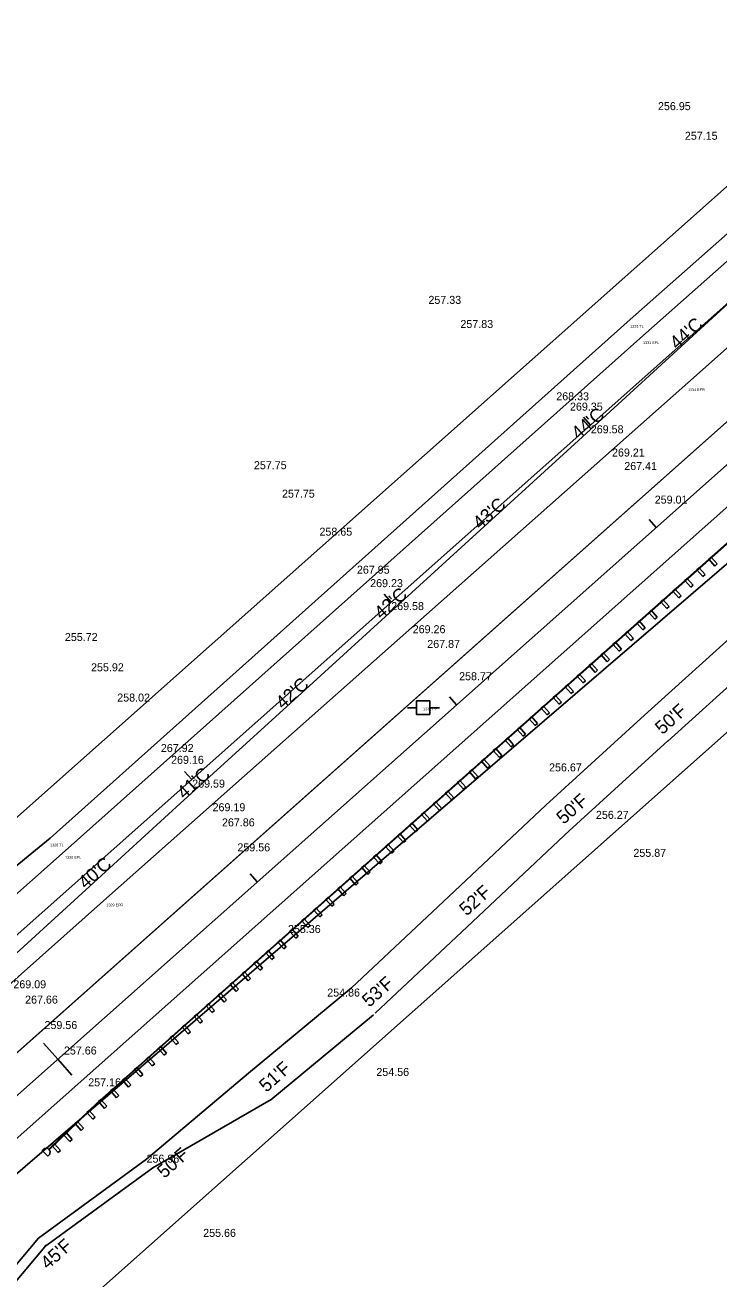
# Model space of a CAD drawing. Extents: x 49683 to 58852, y 49525 to 54803.
# Drawn here: x 52930.9 to 53191, y 50894.8 to 51364.8 of the extents above; entities that cross this region are included whole.
import ezdxf

# ---------------------------------------------------------------- set-up
doc = ezdxf.new("R2010")
doc.units = 0
for name, color, linetype in [('Level 1', 7, 'Continuous'), ('Level 11', 7, 'Continuous'), ('Level 13', 7, 'Continuous'), ('Level 18', 7, 'Continuous'), ('Level 19', 7, 'Continuous'), ('Level 20', 7, 'Continuous'), ('Level 27', 7, 'Continuous'), ('Level 3', 7, 'Continuous'), ('Level 32', 7, 'Continuous'), ('Level 33', 7, 'Continuous'), ('Level 48', 7, 'Continuous'), ('Level 53', 7, 'Continuous'), ('Level 59', 7, 'Continuous'), ('Level 61', 7, 'Continuous'), ('Level 9', 7, 'Continuous')]:
    doc.layers.add(name, color=color, linetype=linetype)

# ---------------------------------------------------------------- blocks, each defined once
blk = doc.blocks.new('PP')
at = {"layer": 'Level 9'}
for p, q in [((2.53, 2.45), (-2.47, 2.45)), ((-2.47, 2.45), (-2.47, -2.55)), ((2.53, -2.55), (2.53, 2.45)), ((-5.91, -0.11), (-2.44, -0.11)), ((-2.47, -2.55), (2.53, -2.55)), ((2.45, -0.11), (6.09, -0.11))]:
    blk.add_line(p, q, dxfattribs=at)

msp = doc.modelspace()

# ---------------------------------------------------------------- linework, layer by layer
at = {"layer": 'Level 1'}
for p, q in [((52544.81, 50683.3), (55534.58, 53340.86)), ((53142.87, 51214.91), (53140.21, 51217.9)), ((53068.13, 51148.47), (53065.47, 51151.46)), ((52993.38, 51082.03), (52990.73, 51085.02))]:
    msp.add_line(p, q, dxfattribs=at)
at = {"layer": 'Level 11'}
for p, q in [((53157.7, 51254.45), (53424.49, 51490.93)), ((52940.3, 51059.99), (53157.7, 51254.45)), ((52882.73, 50895.61), (53245.86, 51207.55)), ((52688.43, 50854.08), (52940.3, 51059.99))]:
    msp.add_line(p, q, dxfattribs=at)
at = {"layer": 'Level 13'}
for p, q in [((52637.37, 50809.73), (53363.85, 51455.49)), ((53407.7, 51406.16), (52566.74, 50658.64))]:
    msp.add_line(p, q, dxfattribs=at)
at = {"layer": 'Level 18'}
for p, q in [((53175.25, 51242.97), (53212.1, 51276.77)), ((53138.39, 51209.17), (53175.25, 51242.97)), ((53101.44, 51175.48), (53138.39, 51209.17)), ((53064.5, 51141.78), (53101.44, 51175.48)), ((53027.57, 51108.07), (53064.5, 51141.78)), ((53163.11, 51106.1), (53200.16, 51139.69)), ((53171.84, 51096.47), (53208.89, 51130.05)), ((52990.61, 51074.38), (53027.57, 51108.07)), ((53126.12, 51072.45), (53163.11, 51106.1)), ((53134.87, 51062.84), (53171.86, 51096.49)), ((52953.66, 51040.7), (52990.61, 51074.38)), ((53089.73, 51038.14), (53126.12, 51072.45)), ((53098.65, 51028.68), (53135.04, 51063)), ((52916.76, 51006.95), (52953.66, 51040.7)), ((53053.26, 51003.9), (53089.73, 51038.14)), ((53062.16, 50994.42), (53098.63, 51028.66)), ((53014.71, 50972.01), (53053.26, 51003.9)), ((53023, 50961.99), (53061.55, 50993.88)), ((52976.49, 50939.75), (53014.71, 50972.01)), ((52978.85, 50936.52), (53023.1, 50962.08)), ((52935.91, 50910.15), (52976.49, 50939.75)), ((52938.27, 50906.92), (52978.85, 50936.52)), ((52903.42, 50871.43), (52935.91, 50910.15)), ((52906.49, 50868.86), (52938.97, 50907.58))]:
    msp.add_line(p, q, dxfattribs=at)
at = {"layer": 'Level 19'}
for p, q in [((52714.15, 50773.62), (54181.77, 52078.16)), ((53167.42, 51176.52), (53164.76, 51179.51)), ((53092.67, 51110.08), (53090.02, 51113.07)), ((53017.93, 51043.65), (53015.28, 51046.64)), ((52943.19, 50977.21), (52937.88, 50983.19)), ((52943.19, 50977.21), (52948.51, 50971.23))]:
    msp.add_line(p, q, dxfattribs=at)
at = {"layer": 'Level 20'}
for p, q in [((52706.17, 50782.58), (53452.43, 51445.92)), ((52722.12, 50764.65), (53468.37, 51427.98))]:
    msp.add_line(p, q, dxfattribs=at)
at = {"layer": 'Level 27'}
for p, q in [((52957.81, 50960.77), (53475.02, 51420.51)), ((52957.97, 50960.58), (53475.18, 51420.32)), ((53187.13, 51164.61), (53188.01, 51165.39)), ((53189.39, 51162.06), (53187.13, 51164.61)), ((53188.01, 51165.39), (53190.27, 51162.85)), ((53190.27, 51162.85), (53189.39, 51162.06)), ((53178.16, 51156.63), (53179.04, 51157.42)), ((53179.04, 51157.42), (53181.3, 51154.88)), ((53182.64, 51160.62), (53183.53, 51161.41)), ((53184.9, 51158.08), (53182.64, 51160.62)), ((53183.53, 51161.41), (53185.79, 51158.86)), ((53185.79, 51158.86), (53184.9, 51158.08)), ((53173.67, 51152.65), (53174.56, 51153.43)), ((53175.93, 51150.11), (53173.67, 51152.65)), ((53174.56, 51153.43), (53176.82, 51150.89)), ((53180.42, 51154.09), (53178.16, 51156.63)), ((53181.3, 51154.88), (53180.42, 51154.09)), ((53169.19, 51148.66), (53170.07, 51149.45)), ((53171.45, 51146.12), (53169.19, 51148.66)), ((53170.07, 51149.45), (53172.33, 51146.91)), ((53176.82, 51150.89), (53175.93, 51150.11)), ((53164.71, 51144.68), (53165.59, 51145.46)), ((53166.96, 51142.13), (53164.71, 51144.68)), ((53165.59, 51145.46), (53167.85, 51142.92)), ((53167.85, 51142.92), (53166.96, 51142.13)), ((53172.33, 51146.91), (53171.45, 51146.12)), ((53160.22, 51140.69), (53161.1, 51141.47)), ((53162.48, 51138.15), (53160.22, 51140.69)), ((53161.1, 51141.47), (53163.36, 51138.93)), ((53163.36, 51138.93), (53162.48, 51138.15)), ((53151.25, 51132.72), (53152.14, 51133.5)), ((53152.14, 51133.5), (53154.39, 51130.96)), ((53155.74, 51136.7), (53156.62, 51137.49)), ((53157.99, 51134.16), (53155.74, 51136.7)), ((53156.62, 51137.49), (53158.88, 51134.95)), ((53158.88, 51134.95), (53157.99, 51134.16)), ((53146.77, 51128.73), (53147.65, 51129.52)), ((53149.03, 51126.19), (53146.77, 51128.73)), ((53147.65, 51129.52), (53149.91, 51126.97)), ((53153.51, 51130.18), (53151.25, 51132.72)), ((53154.39, 51130.96), (53153.51, 51130.18)), ((53142.28, 51124.74), (53143.17, 51125.53)), ((53144.54, 51122.2), (53142.28, 51124.74)), ((53143.17, 51125.53), (53145.43, 51122.99)), ((53149.91, 51126.97), (53149.03, 51126.19)), ((53137.8, 51120.76), (53138.68, 51121.54)), ((53140.06, 51118.22), (53137.8, 51120.76)), ((53138.68, 51121.54), (53140.94, 51119)), ((53145.43, 51122.99), (53144.54, 51122.2)), ((53133.31, 51116.77), (53134.2, 51117.56)), ((53135.57, 51114.23), (53133.31, 51116.77)), ((53134.2, 51117.56), (53136.46, 51115.02)), ((53136.46, 51115.02), (53135.57, 51114.23)), ((53140.94, 51119), (53140.06, 51118.22)), ((53128.83, 51112.79), (53129.71, 51113.57)), ((53131.09, 51110.24), (53128.83, 51112.79)), ((53129.71, 51113.57), (53131.97, 51111.03)), ((53131.97, 51111.03), (53131.09, 51110.24)), ((53119.86, 51104.81), (53120.74, 51105.6)), ((53120.74, 51105.6), (53123, 51103.06)), ((53124.35, 51108.8), (53125.23, 51109.58)), ((53126.6, 51106.26), (53124.35, 51108.8)), ((53125.23, 51109.58), (53127.49, 51107.04)), ((53127.49, 51107.04), (53126.6, 51106.26)), ((53115.38, 51100.83), (53116.26, 51101.61)), ((53117.63, 51098.29), (53115.38, 51100.83)), ((53116.26, 51101.61), (53118.52, 51099.07)), ((53122.12, 51102.27), (53119.86, 51104.81)), ((53123, 51103.06), (53122.12, 51102.27)), ((53110.89, 51096.84), (53111.78, 51097.63)), ((53113.15, 51094.3), (53110.89, 51096.84)), ((53111.78, 51097.63), (53114.03, 51095.08)), ((53118.52, 51099.07), (53117.63, 51098.29)), ((53106.41, 51092.86), (53107.29, 51093.64)), ((53108.67, 51090.31), (53106.41, 51092.86)), ((53107.29, 51093.64), (53109.55, 51091.1)), ((53109.55, 51091.1), (53108.67, 51090.31)), ((53114.03, 51095.08), (53113.15, 51094.3)), ((53101.92, 51088.87), (53102.81, 51089.65)), ((53104.18, 51086.33), (53101.92, 51088.87)), ((53102.81, 51089.65), (53105.06, 51087.11)), ((53105.06, 51087.11), (53104.18, 51086.33)), ((53092.95, 51080.9), (53093.84, 51081.68)), ((53093.84, 51081.68), (53096.1, 51079.14)), ((53097.44, 51084.88), (53098.32, 51085.67)), ((53099.7, 51082.34), (53097.44, 51084.88)), ((53098.32, 51085.67), (53100.58, 51083.13)), ((53100.58, 51083.13), (53099.7, 51082.34)), ((53088.47, 51076.91), (53089.35, 51077.7)), ((53090.73, 51074.37), (53088.47, 51076.91)), ((53089.35, 51077.7), (53091.61, 51075.15)), ((53095.21, 51078.36), (53092.95, 51080.9)), ((53096.1, 51079.14), (53095.21, 51078.36)), ((53083.99, 51072.92), (53084.87, 51073.71)), ((53086.24, 51070.38), (53083.99, 51072.92)), ((53084.87, 51073.71), (53087.13, 51071.17)), ((53091.61, 51075.15), (53090.73, 51074.37)), ((53079.5, 51068.94), (53080.38, 51069.72)), ((53081.76, 51066.4), (53079.5, 51068.94)), ((53080.38, 51069.72), (53082.64, 51067.18)), ((53087.13, 51071.17), (53086.24, 51070.38)), ((53075.02, 51064.95), (53075.9, 51065.74)), ((53077.27, 51062.41), (53075.02, 51064.95)), ((53075.9, 51065.74), (53078.16, 51063.2)), ((53078.16, 51063.2), (53077.27, 51062.41)), ((53082.64, 51067.18), (53081.76, 51066.4)), ((53070.53, 51060.97), (53071.42, 51061.75)), ((53072.79, 51058.42), (53070.53, 51060.97)), ((53071.42, 51061.75), (53073.67, 51059.21)), ((53073.67, 51059.21), (53072.79, 51058.42)), ((53061.56, 51052.99), (53062.45, 51053.78)), ((53062.45, 51053.78), (53064.7, 51051.24)), ((53066.05, 51056.98), (53066.93, 51057.76)), ((53068.31, 51054.44), (53066.05, 51056.98)), ((53066.93, 51057.76), (53069.19, 51055.22)), ((53069.19, 51055.22), (53068.31, 51054.44)), ((53057.08, 51049.01), (53057.96, 51049.79)), ((53059.34, 51046.47), (53057.08, 51049.01)), ((53057.96, 51049.79), (53060.22, 51047.25)), ((53063.82, 51050.45), (53061.56, 51052.99)), ((53064.7, 51051.24), (53063.82, 51050.45)), ((53052.59, 51045.02), (53053.48, 51045.81)), ((53054.85, 51042.48), (53052.59, 51045.02)), ((53053.48, 51045.81), (53055.74, 51043.26)), ((53060.22, 51047.25), (53059.34, 51046.47)), ((53048.11, 51041.03), (53048.99, 51041.82)), ((53050.37, 51038.49), (53048.11, 51041.03)), ((53048.99, 51041.82), (53051.25, 51039.28)), ((53051.25, 51039.28), (53050.37, 51038.49)), ((53055.74, 51043.26), (53054.85, 51042.48)), ((53043.62, 51037.05), (53044.51, 51037.83)), ((53045.88, 51034.51), (53043.62, 51037.05)), ((53044.51, 51037.83), (53046.77, 51035.29)), ((53046.77, 51035.29), (53045.88, 51034.51)), ((53034.66, 51029.08), (53035.54, 51029.86)), ((53035.54, 51029.86), (53037.8, 51027.32)), ((53039.14, 51033.06), (53040.02, 51033.85)), ((53041.4, 51030.52), (53039.14, 51033.06)), ((53040.02, 51033.85), (53042.28, 51031.31)), ((53042.28, 51031.31), (53041.4, 51030.52)), ((53030.17, 51025.09), (53031.05, 51025.88)), ((53031.05, 51025.88), (53033.31, 51023.33)), ((53036.91, 51026.53), (53034.66, 51029.08)), ((53037.8, 51027.32), (53036.91, 51026.53)), ((53025.69, 51021.1), (53026.57, 51021.89)), ((53027.95, 51018.56), (53025.69, 51021.1)), ((53026.57, 51021.89), (53028.83, 51019.35)), ((53032.43, 51022.55), (53030.17, 51025.09)), ((53033.31, 51023.33), (53032.43, 51022.55)), ((53021.2, 51017.12), (53022.09, 51017.9)), ((53023.46, 51014.58), (53021.2, 51017.12)), ((53022.09, 51017.9), (53024.34, 51015.36)), ((53028.83, 51019.35), (53027.95, 51018.56)), ((53016.72, 51013.13), (53017.6, 51013.92)), ((53018.98, 51010.59), (53016.72, 51013.13)), ((53017.6, 51013.92), (53019.86, 51011.38)), ((53019.86, 51011.38), (53018.98, 51010.59)), ((53024.34, 51015.36), (53023.46, 51014.58)), ((53012.23, 51009.15), (53013.12, 51009.93)), ((53014.49, 51006.6), (53012.23, 51009.15)), ((53013.12, 51009.93), (53015.38, 51007.39)), ((53015.38, 51007.39), (53014.49, 51006.6)), ((53003.26, 51001.17), (53004.15, 51001.96)), ((53004.15, 51001.96), (53006.41, 50999.42)), ((53007.75, 51005.16), (53008.63, 51005.94)), ((53010.01, 51002.62), (53007.75, 51005.16)), ((53008.63, 51005.94), (53010.89, 51003.4)), ((53010.89, 51003.4), (53010.01, 51002.62)), ((52998.78, 50997.19), (52999.66, 50997.97)), ((53001.04, 50994.65), (52998.78, 50997.19)), ((52999.66, 50997.97), (53001.92, 50995.43)), ((53005.52, 50998.63), (53003.26, 51001.17)), ((53006.41, 50999.42), (53005.52, 50998.63)), ((52994.3, 50993.2), (52995.18, 50993.99)), ((52996.55, 50990.66), (52994.3, 50993.2)), ((52995.18, 50993.99), (52997.44, 50991.44)), ((53001.92, 50995.43), (53001.04, 50994.65)), ((52989.81, 50989.21), (52990.69, 50990)), ((52992.07, 50986.67), (52989.81, 50989.21)), ((52990.69, 50990), (52992.95, 50987.46)), ((52997.44, 50991.44), (52996.55, 50990.66)), ((52985.33, 50985.23), (52986.21, 50986.01)), ((52987.59, 50982.69), (52985.33, 50985.23)), ((52986.21, 50986.01), (52988.47, 50983.47)), ((52988.47, 50983.47), (52987.59, 50982.69)), ((52992.95, 50987.46), (52992.07, 50986.67)), ((52980.84, 50981.24), (52981.73, 50982.03)), ((52983.1, 50978.7), (52980.84, 50981.24)), ((52981.73, 50982.03), (52983.98, 50979.49)), ((52983.98, 50979.49), (52983.1, 50978.7)), ((52971.87, 50973.27), (52972.76, 50974.06)), ((52972.76, 50974.06), (52975.02, 50971.51)), ((52976.36, 50977.26), (52977.24, 50978.04)), ((52978.62, 50974.71), (52976.36, 50977.26)), ((52977.24, 50978.04), (52979.5, 50975.5)), ((52979.5, 50975.5), (52978.62, 50974.71)), ((52967.39, 50969.28), (52968.27, 50970.07)), ((52969.65, 50966.74), (52967.39, 50969.28)), ((52968.27, 50970.07), (52970.53, 50967.53)), ((52974.13, 50970.73), (52971.87, 50973.27)), ((52975.02, 50971.51), (52974.13, 50970.73)), ((52962.9, 50965.3), (52963.79, 50966.08)), ((52965.16, 50962.76), (52962.9, 50965.3)), ((52963.79, 50966.08), (52966.05, 50963.54)), ((52970.53, 50967.53), (52969.65, 50966.74)), ((52957.81, 50960.77), (52939.79, 50943.41)), ((52957.98, 50960.59), (52939.96, 50943.23)), ((52958.42, 50961.31), (52959.3, 50962.1)), ((52960.68, 50958.77), (52958.42, 50961.31)), ((52959.3, 50962.1), (52961.56, 50959.56)), ((52961.56, 50959.56), (52960.68, 50958.77)), ((52966.05, 50963.54), (52965.16, 50962.76)), ((52954.04, 50957.21), (52954.93, 50957.99)), ((52956.3, 50954.66), (52954.04, 50957.21)), ((52954.93, 50957.99), (52957.18, 50955.45)), ((52957.18, 50955.45), (52956.3, 50954.66)), ((52949.72, 50953.04), (52950.6, 50953.83)), ((52951.98, 50950.5), (52949.72, 50953.04)), ((52950.6, 50953.83), (52952.86, 50951.28)), ((52952.86, 50951.28), (52951.98, 50950.5)), ((52941.07, 50944.71), (52941.95, 50945.49)), ((52941.95, 50945.49), (52944.21, 50942.95)), ((52945.39, 50948.87), (52946.28, 50949.66)), ((52947.65, 50946.33), (52945.39, 50948.87)), ((52946.28, 50949.66), (52948.53, 50947.12)), ((52948.53, 50947.12), (52947.65, 50946.33)), ((52943.33, 50942.17), (52941.07, 50944.71)), ((52944.21, 50942.95), (52943.33, 50942.17))]:
    msp.add_line(p, q, dxfattribs=at)
msp.add_lwpolyline([(52938.11, 50943.7), (52939.35, 50943.86), (52940.4, 50942.78), (52940.2, 50941.55), (52939.48, 50940.85), (52937.39, 50943.01)], close=True, dxfattribs=at)
at = {"layer": 'Level 3'}
for p, q in [((53162.5, 51248.32), (53434.09, 51489.84)), ((53179.35, 51230.72), (53449.72, 51471.81)), ((52945.93, 51055.32), (53162.5, 51248.32)), ((52961.4, 51037.52), (53179.35, 51230.72)), ((52676.2, 50815.96), (52945.93, 51055.32)), ((52668.7, 50777.53), (52961.4, 51037.52))]:
    msp.add_line(p, q, dxfattribs=at)
at = {"layer": 'Level 33'}
msp.add_line((52768.8, 50721.85), (53711.35, 51559.67), dxfattribs=at)

# ---------------------------------------------------------------- block references
at = {"layer": 'Level 9'}
msp.add_blockref('PP', (53080.11, 51109.02), dxfattribs=at)

# ---------------------------------------------------------------- texts
at = {"layer": 'Level 32'}
for s, p in [('256.95', (53168.11, 51332.96)), ('257.15', (53178.19, 51321.85)), ('257.33', (53082.09, 51260.33)), ('257.83', (53094.07, 51251.3)), ('268.33', (53130, 51224.2)), ('269.35', (53135.14, 51220.32)), ('269.58', (53142.94, 51211.82)), ('269.21', (53150.89, 51203.11)), ('257.75', (53016.69, 51198.37)), ('267.41', (53155.48, 51198.05)), ('257.75', (53027.22, 51187.69)), ('259.01', (53166.9, 51185.46)), ('258.65', (53041.25, 51173.44)), ('267.95', (53055.29, 51159.19)), ('269.23', (53060.26, 51154.15)), ('269.58', (53068.14, 51145.55)), ('269.26', (53076.2, 51136.88)), ('255.72', (52945.85, 51133.95)), ('267.87', (53081.65, 51131.36)), ('255.92', (52955.66, 51122.61)), ('258.77', (53093.59, 51119.26)), ('258.02', (52965.47, 51111.26)), ('267.92', (52981.82, 51092.35)), ('269.16', (52985.65, 51087.92)), ('256.67', (53127.3, 51085.08)), ('269.59', (52993.56, 51079)), ('269.19', (53001.2, 51070.15)), ('267.86', (53004.72, 51064.47)), ('256.27', (53144.86, 51067.29)), ('259.56', (53010.5, 51055.11)), ('255.87', (53158.9, 51053.05)), ('255.36', (53029.44, 51024.49)), ('269.09', (52926.55, 51003.78)), ('254.86', (53044.17, 51000.68)), ('267.66', (52930.94, 50998.03)), ('259.56', (52938.22, 50988.49)), ('257.66', (52945.5, 50978.95)), ('254.56', (53062.58, 50970.91)), ('257.16', (52954.6, 50967.03)), ('256.96', (52976.44, 50938.41)), ('255.66', (52997.68, 50910.59))]:
    msp.add_text(s, height=3, dxfattribs=at).set_placement(p)
at = {"layer": 'Level 48'}
for s, rotation, p in [("44'C", 41.6334, (53175.25, 51242.97)), ("44'C", 41.6334, (53138.39, 51209.17)), ("43'C", 41.6334, (53101.44, 51175.48)), ("42'C", 41.6334, (53064.5, 51141.78)), ("42'C", 41.6334, (53027.57, 51108.07)), ("50'F", 41.6333, (53169.75, 51098.63)), ("41'C", 41.6334, (52990.61, 51074.38)), ("50'F", 41.6334, (53132.77, 51064.98)), ("40'C", 41.6334, (52953.66, 51040.7)), ("52'F", 41.6334, (53096.37, 51030.66)), ("53'F", 41.6333, (53059.91, 50996.43)), ("51'F", 41.6334, (53021.36, 50964.54)), ("50'F", 41.6334, (52983.13, 50932.28)), ("45'F", 41.6334, (52939.45, 50898.09))]:
    msp.add_text(s, height=5, rotation=rotation, dxfattribs=at).set_placement(p)
at = {"layer": 'Level 53'}
for s, p in [('1331 EPL', (53162.5, 51245.32)), ('1334 EPR', (53179.35, 51227.72)), ('1330 EPL', (52945.93, 51052.32)), ('1329 EPR', (52961.4, 51034.52))]:
    msp.add_text(s, height=1, dxfattribs=at).set_placement(p)
at = {"layer": 'Level 59'}
msp.add_text('1332 PP', height=1, dxfattribs=at).set_placement((53080.11, 51108.02))
at = {"layer": 'Level 61'}
for s, p in [('1333 TL', (53157.7, 51251.45)), ('1328 TL', (52940.3, 51056.99))]:
    msp.add_text(s, height=1, dxfattribs=at).set_placement(p)

doc.saveas('drawing.dxf')
